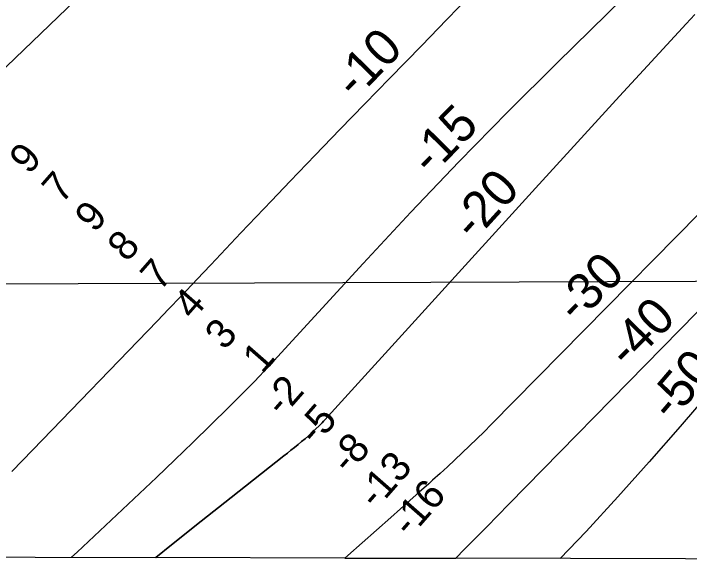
# Model space of a CAD drawing. Extents: x 3172297 to 3210190, y 958463 to 983887.
# Drawn here: x 3194156 to 3195699, y 963866 to 965117 of the extents above; entities that cross this region are included whole.
import ezdxf

# ---------------------------------------------------------------- set-up
doc = ezdxf.new("R2010")
doc.units = 0
for name, color, linetype in [('V-RIVR-RANG', 7, 'Continuous'), ('V-TOPO-BNDY', 7, 'Continuous'), ('V-TOPO-DPTH', 7, 'Continuous'), ('V-TOPO-MAJR', 7, 'Continuous'), ('V-TOPO-MAJR-IDEN', 7, 'Continuous'), ('V-TOPO-MINR', 7, 'Continuous'), ('V-TOPO-MINR-IDEN', 7, 'Continuous')]:
    doc.layers.add(name, color=color, linetype=linetype)

msp = doc.modelspace()

# ---------------------------------------------------------------- linework, layer by layer
at = {"layer": 'V-TOPO-BNDY'}
msp.add_lwpolyline([(3186048.8, 963896), (3186249.6, 964470), (3198733.3, 964517.6), (3198114.7, 963866.1)], dxfattribs=at)
at = {"layer": 'V-TOPO-DPTH'}
for points in [[(3195200.9, 965160.8), (3195144.8, 965102.1), (3195088.2, 965043.7), (3195014.9, 964968.7), (3194958, 964910.3), (3194901.2, 964851.8), (3194844.6, 964793.1), (3194788.2, 964734.4), (3194745.1, 964689.3), (3194710.3, 964652.9), (3194675.6, 964616.4), (3194641.1, 964579.9), (3194606.5, 964543.2), (3194590, 964525.6), (3194563.7, 964497.8), (3194537.4, 964470), (3194511, 964442.4), (3194484.6, 964414.8), (3194200.9, 964120.6), (3194152.4, 964071.8)], [(3194152.4, 964071.8), (3194200.9, 964120.6), (3194484.6, 964414.8), (3194511, 964442.4), (3194537.4, 964470), (3194563.7, 964497.8), (3194590, 964525.6), (3194606.5, 964543.2), (3194641.1, 964579.9), (3194675.6, 964616.4), (3194710.3, 964652.9), (3194745.1, 964689.3), (3194788.2, 964734.4), (3194844.6, 964793.1), (3194901.2, 964851.8), (3194958, 964910.3), (3195014.9, 964968.7), (3195088.2, 965043.7), (3195144.8, 965102.1), (3195200.9, 965160.8)], [(3193929.4, 963876.5), (3194481.2, 963875.1), (3194516.8, 963903.9), (3194584.8, 963958.2), (3194653, 964012.3), (3194773.3, 964107.2), (3194781.5, 964113.6), (3194789.7, 964120.1), (3194797.8, 964126.5), (3194806, 964133), (3194814.1, 964139.6), (3194822, 964146.3), (3194829.8, 964153.2), (3194837.5, 964160.3), (3194854.5, 964176.3), (3194857.8, 964179.4), (3194861, 964182.7), (3194864.2, 964186), (3194867.3, 964189.3), (3195347.7, 964718.3), (3195411.4, 964788.3), (3195475.3, 964858.2), (3195539.2, 964928), (3195603.3, 964997.6), (3195691.3, 965093), (3195711.5, 965114.9)], [(3194912.6, 963874), (3194481.2, 963875.1), (3194516.8, 963903.9), (3194584.8, 963958.2), (3194653, 964012.3), (3194773.3, 964107.2), (3194781.5, 964113.6), (3194789.7, 964120.1), (3194797.8, 964126.5), (3194806, 964133), (3194814.1, 964139.6), (3194822, 964146.3), (3194829.8, 964153.2), (3194837.5, 964160.3), (3194854.5, 964176.3), (3194857.8, 964179.4), (3194861, 964182.7), (3194864.2, 964186), (3194867.3, 964189.3), (3195347.7, 964718.3), (3195411.4, 964788.3), (3195475.3, 964858.2), (3195539.2, 964928), (3195603.3, 964997.6), (3195691.3, 965093), (3195711.5, 965114.9)], [(3195933.9, 964875.4), (3195246.7, 964178.4), (3195230.4, 964162.1), (3195214, 964145.8), (3195197.5, 964129.8), (3195180.8, 964113.8), (3195164, 964098), (3195147.1, 964082.3), (3195130.1, 964066.8), (3195112.9, 964051.4), (3195104.2, 964043.6), (3195082.5, 964024.4), (3195060.9, 964005.2), (3195039.3, 963986), (3195017.6, 963966.8), (3194919.4, 963880), (3194912.6, 963874)], [(3195933.9, 964875.4), (3195246.7, 964178.4), (3195230.4, 964162.1), (3195214, 964145.8), (3195197.5, 964129.8), (3195180.8, 964113.8), (3195164, 964098), (3195147.1, 964082.3), (3195130.1, 964066.8), (3195112.9, 964051.4), (3195104.2, 964043.6), (3195082.5, 964024.4), (3195060.9, 964005.2), (3195039.3, 963986), (3195017.6, 963966.8), (3194919.4, 963880), (3194912.6, 963874)], [(3194912.6, 963874), (3195165.7, 963873.4), (3195186, 963894.1), (3195236.5, 963945.3), (3195286.9, 963996.6), (3195988.5, 964712.1)], [(3195165.7, 963873.4), (3195186, 963894.1), (3195236.5, 963945.3), (3195286.9, 963996.6), (3195988.5, 964712.1)], [(3196476.3, 963870.2), (3195165.7, 963873.4)]]:
    msp.add_lwpolyline(points, dxfattribs=at)
at = {"layer": 'V-TOPO-MAJR'}
msp.add_lwpolyline([(3195747.9, 964255.4), (3195678.2, 964173.9), (3195607.6, 964093.2), (3195535.8, 964013.6), (3195463.1, 963934.7), (3195404.2, 963872.8)], dxfattribs=at)
at = {"layer": 'V-TOPO-MINR'}
for points in [[(3195825.9, 965508), (3195624.5, 965227.6), (3195397, 965004.5), (3195284.3, 964892.1), (3195172.7, 964778.4), (3195063, 964663.1), (3194954.5, 964546.5), (3194750.6, 964323.8), (3194739.6, 964312), (3194728.6, 964300.3), (3194717.4, 964288.7), (3194706.1, 964277.2), (3194647.6, 964218.6), (3194606.8, 964178), (3194565.7, 964137.7), (3194524.3, 964097.8), (3194482.6, 964058.1), (3194301.4, 963887.2), (3194289.1, 963875.6)], [(3194337.3, 965186), (3194060.2, 964919.6)], [(3195200.9, 965160.8), (3195144.8, 965102.1), (3195088.2, 965043.7), (3195014.9, 964968.7), (3194958, 964910.3), (3194901.2, 964851.8), (3194844.6, 964793.1), (3194788.2, 964734.4), (3194745.1, 964689.3), (3194710.3, 964652.9), (3194675.6, 964616.4), (3194641.1, 964579.9), (3194606.5, 964543.2), (3194590, 964525.6), (3194563.7, 964497.8), (3194537.4, 964470), (3194511, 964442.4), (3194484.6, 964414.8), (3194200.9, 964120.6), (3194152.4, 964071.8)], [(3195711.5, 965114.9), (3195691.3, 965093), (3195603.3, 964997.6), (3195539.2, 964928), (3195475.3, 964858.2), (3195411.4, 964788.3), (3195347.7, 964718.3), (3194867.3, 964189.3), (3194864.2, 964186), (3194861, 964182.7), (3194857.8, 964179.4), (3194854.5, 964176.3), (3194837.5, 964160.3), (3194829.8, 964153.2), (3194822, 964146.3), (3194814.1, 964139.6), (3194806, 964133), (3194797.8, 964126.5), (3194789.7, 964120.1), (3194781.5, 964113.6), (3194773.3, 964107.2), (3194653, 964012.3), (3194584.8, 963958.2), (3194516.8, 963903.9), (3194481.2, 963875.1)], [(3195933.9, 964875.4), (3195246.7, 964178.4), (3195230.4, 964162.1), (3195214, 964145.8), (3195197.5, 964129.8), (3195180.8, 964113.8), (3195164, 964098), (3195147.1, 964082.3), (3195130.1, 964066.8), (3195112.9, 964051.4), (3195104.2, 964043.6), (3195082.5, 964024.4), (3195060.9, 964005.2), (3195039.3, 963986), (3195017.6, 963966.8), (3194919.4, 963880), (3194912.6, 963874)], [(3195988.5, 964712.1), (3195286.9, 963996.6), (3195236.5, 963945.3), (3195186, 963894.1), (3195165.7, 963873.4)]]:
    msp.add_lwpolyline(points, dxfattribs=at)

# ---------------------------------------------------------------- texts
at = {"layer": 'V-RIVR-RANG'}
for s, p in [('9', (3194191.6, 964747.1)), ('7', (3194266.2, 964680.5)), ('9', (3194341.2, 964614.3)), ('8', (3194415.4, 964547.3)), ('7', (3194490.6, 964481.3)), ('4', (3194565.5, 964415.1)), ('3', (3194638, 964346.1)), ('1', (3194724.1, 964292.6)), ('-2', (3194770.5, 964193.8)), ('-5', (3194846, 964128.2)), ('-8', (3194921.5, 964062.6)), ('-13', (3194984.4, 963982.7)), ('-16', (3195061.3, 963918.7))]:
    msp.add_text(s, height=67, rotation=48.82, dxfattribs=at).set_placement(p)
at = {"layer": 'V-TOPO-MAJR-IDEN'}
msp.add_text('-50', height=83, rotation=49.459, dxfattribs=at).set_placement((3195658.3, 964182.6))
at = {"layer": 'V-TOPO-MINR-IDEN'}
for s, rotation, p in [('-10', 45.7391, (3194936.7, 964918.2)), ('-15', 45.5238, (3195109.5, 964743.7)), ('-20', 47.7564, (3195207.6, 964594.9)), ('-30', 45.406, (3195442.6, 964406.7)), ('-40', 45.5611, (3195559.2, 964303.9))]:
    msp.add_text(s, height=83, rotation=rotation, dxfattribs=at).set_placement(p)

doc.saveas('drawing.dxf')
